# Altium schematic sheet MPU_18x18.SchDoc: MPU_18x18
size A3; DocumentNumber: MB1263; Revision: C-04; SheetNumber: 3; SheetTotal: 11; Project: STM32MP157-EVAL
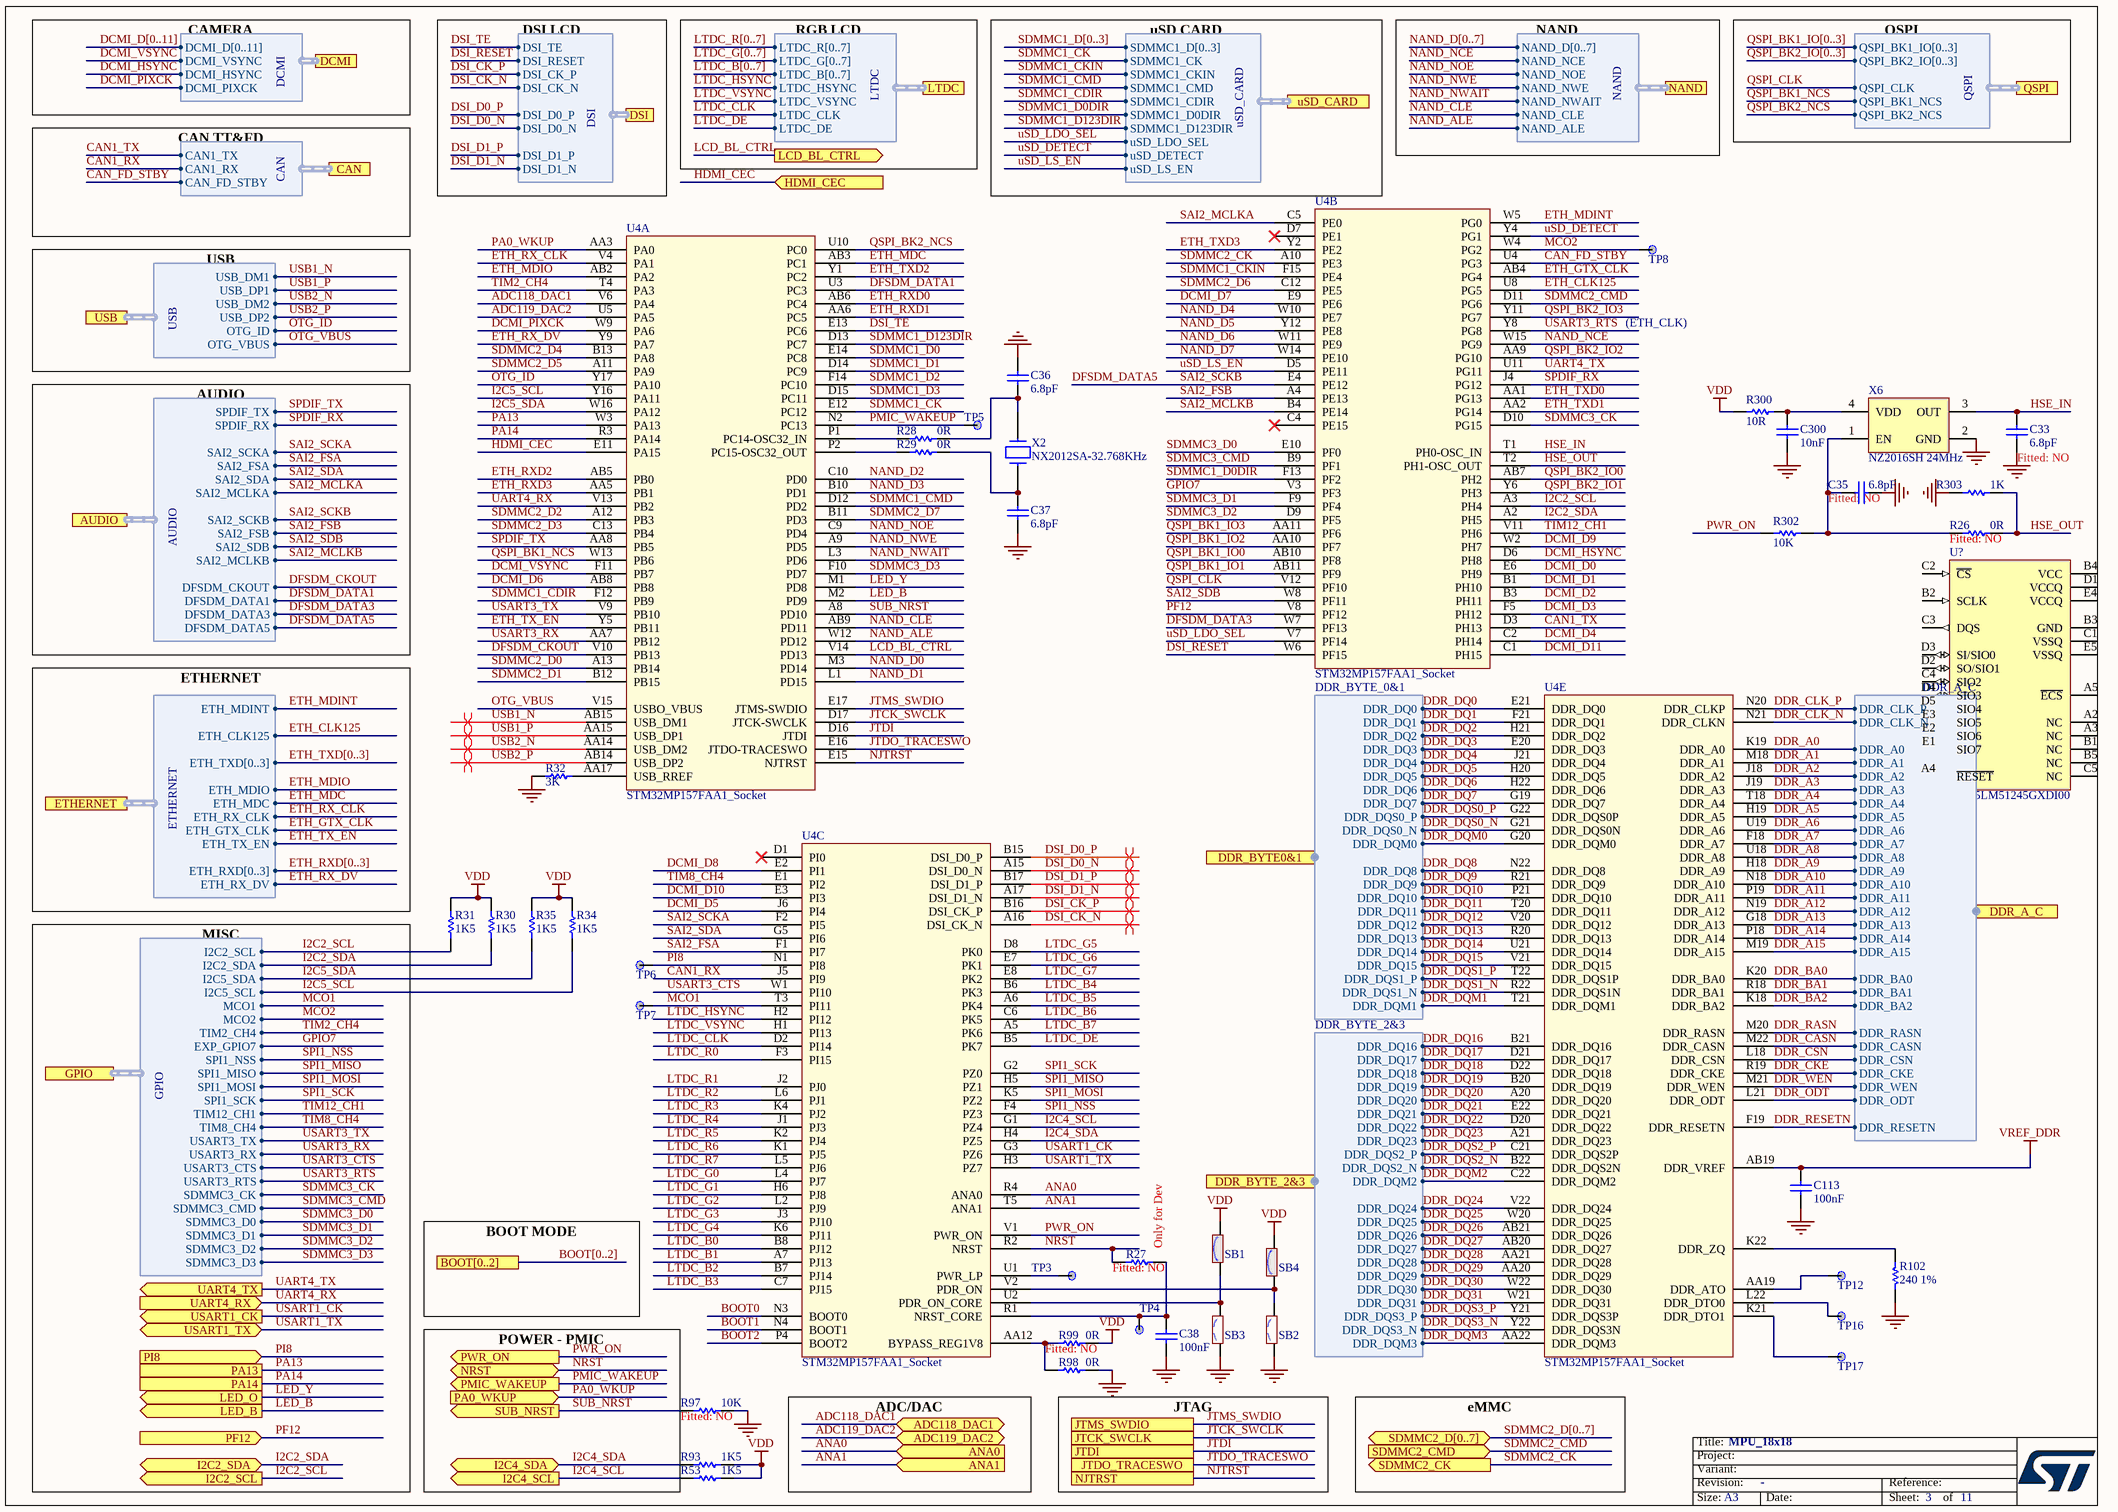
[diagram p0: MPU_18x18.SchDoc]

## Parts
C33  Fitted: NO  [C0402]  (hidden comment: 6.8pF)
C35  Fitted: NO  [C0402]  (hidden comment: 6.8pF)
C36  6.8pF  [C0402]
C37  6.8pF  [C0402]
C38  100nF  [C0402]
C113  100nF  [C0402]
C300  10nF  [C0402]
R26  0R  Fitted: NO  [R0402]
R27  Fitted: NO  [R0402]  (hidden comment: 0R)
R28  0R  [R0402]
R29  0R  [R0402]
R30  1K5  [R0402]
R31  1K5  [R0402]
R32  3K  [R0402]
R34  1K5  [R0402]
R35  1K5  [R0402]
R53  1K5  [R0402]
R93  1K5  [R0402]
R97  10K  Fitted: NO  [R0402]
R98  0R  [R0402]
R99  0R  Fitted: NO  [R0402]
R102  240 1%  [R0402]
R300  value 10R  [R0402]  (hidden comment: Resistor)
R302  10K  [R0402]
R303  1K  [R0402]
SB1  SB_ON  [SOLDER-BRIDGE_R0603-0R]  (value not drawn)
SB2  SB_OFF  [SOLDER-BRIDGE_R0603-0R]  (value not drawn)
SB3  SB_OFF  [SOLDER-BRIDGE_R0603-0R]  (value not drawn)
SB4  SB_ON  [SOLDER-BRIDGE_R0603-0R]  (value not drawn)
TP3  TP  [TP_SMD_1MM]  (value not drawn)  (no BOM)
TP4  TP  [TP_SMD_1MM]  (value not drawn)  (no BOM)
TP5  TP  [TP_SMD_1MM]  (value not drawn)  (no BOM)
TP6  TP  [TP_SMD_1MM]  (value not drawn)  (no BOM)
TP7  TP  [TP_SMD_1MM]  (value not drawn)  (no BOM)
TP8  TP  [TP_SMD_1MM]  (value not drawn)  (no BOM)
TP12  TP 0.6  [TP_SMD_0-6MM]  (value not drawn)  (no BOM)
TP16  TP 0.6  [TP_SMD_0-6MM]  (value not drawn)  (no BOM)
TP17  TP 0.6  [TP_SMD_0-6MM]  (value not drawn)  (no BOM)
U4  STM32MP157FAA1_Socket  [ICC_LFBGA448_18X18_STM32MP157BAA3_P080__SOCKET_IE_CS1627194MF]  (parts A,B,C,E of 5)
U?  value MX25LM51245GXDI00  [ICC_BGA24_5X5-BALL-ARRAY_6X8_P1]  (hidden comment: MX25xx51245GXDx00)
X2  NX2012SA-32.768KHz  [CRY_NX2012SA_2P]
X6  value NZ2016SH 24MHz  [CRY_NZ2016SH_4P]  (hidden comment: OSCILLATOR_4_PINS)

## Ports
ADC118_DAC1 (bidir), ADC119_DAC2 (bidir), ANA0 (in), ANA1 (in), AUDIO (harness AUDIO), BOOT[0..2], CAN (harness CAN), DCMI (harness DCMI), DDR_A_C (harness DDR_A_C), DDR_BYTE0&1 (harness DDR_BYTE_0&1), DDR_BYTE_2&3 (harness DDR_BYTE_2&3), DSI (harness DSI), ETHERNET (harness ETHERNET), GPIO (harness GPIO), HDMI_CEC (in), I2C2_SCL (out), I2C2_SDA (bidir), I2C4_SCL (out), I2C4_SDA (bidir), JTCK_SWCLK, JTDI, JTDO_TRACESWO, JTMS_SWDIO, LCD_BL_CTRL (out), LED_B (out), LED_O (out), LTDC (harness LTDC), NAND (harness NAND), NJTRST, NRST (bidir), PA0_WKUP (in), PA13, PA14, PF12 (in), PI8 (in), PMIC_WAKEUP (out), PWR_ON (out), QSPI (harness QSPI), SDMMC2_CK (out), SDMMC2_CMD (in), SDMMC2_D[0..7] (bidir), SUB_NRST (out), UART4_RX (in), UART4_TX (out), USART1_CK (out), USART1_TX (bidir), USB (harness USB), uSD_CARD (harness uSD_CARD)

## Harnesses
DDR_BYTE_0&1: DDR_DQ0, DDR_DQ1, DDR_DQ2, DDR_DQ3, DDR_DQ4, DDR_DQ5, DDR_DQ6, DDR_DQ7, DDR_DQS0_P, DDR_DQS0_N, DDR_DQM0, DDR_DQ8, DDR_DQ9, DDR_DQ10, DDR_DQ11, DDR_DQ12, DDR_DQ13, DDR_DQ14, DDR_DQ15, DDR_DQS1_P, DDR_DQS1_N, DDR_DQM1
DDR_BYTE_2&3: DDR_DQ16, DDR_DQ17, DDR_DQ18, DDR_DQ19, DDR_DQ20, DDR_DQ21, DDR_DQ22, DDR_DQ23, DDR_DQS2_P, DDR_DQS2_N, DDR_DQM2, DDR_DQ24, DDR_DQ25, DDR_DQ26, DDR_DQ27, DDR_DQ28, DDR_DQ29, DDR_DQ30, DDR_DQ31, DDR_DQS3_P, DDR_DQS3_N, DDR_DQM3
DDR_A_C: DDR_CLK_P, DDR_CLK_N, DDR_A0, DDR_A1, DDR_A2, DDR_A3, DDR_A4, DDR_A5, DDR_A6, DDR_A7, DDR_A8, DDR_A9, DDR_A10, DDR_A11, DDR_A12, DDR_A13, DDR_A14, DDR_A15, DDR_BA0, DDR_BA1, DDR_BA2, DDR_RASN, DDR_CASN, DDR_CSN, DDR_CKE, DDR_WEN, DDR_ODT, DDR_RESETN
GPIO: I2C2_SCL, I2C2_SDA, I2C5_SDA, MCO1, MCO2, TIM2_CH4, EXP_GPIO7, SPI1_NSS, SPI1_MISO, SPI1_MOSI, SPI1_SCK, TIM12_CH1, TIM8_CH4, USART3_TX, USART3_RX, USART3_CTS, USART3_RTS, SDMMC3_CK, SDMMC3_CMD, SDMMC3_D0, SDMMC3_D1, SDMMC3_D2, SDMMC3_D3, I2C5_SCL
ETHERNET: ETH_MDINT, ETH_CLK125, ETH_TXD[0..3], ETH_MDIO, ETH_MDC, ETH_RX_CLK, ETH_GTX_CLK, ETH_TX_EN, ETH_RXD[0..3], ETH_RX_DV
AUDIO: SPDIF_TX, SPDIF_RX, SAI2_SCKA, SAI2_FSA, SAI2_SDA, SAI2_SDB, SAI2_MCLKA, DFSDM_CKOUT, DFSDM_DATA1, DFSDM_DATA3, DFSDM_DATA5, SAI2_SCKB, SAI2_FSB, SAI2_MCLKB
DCMI: DCMI_D[0..11], DCMI_VSYNC, DCMI_HSYNC, DCMI_PIXCK
DSI: DSI_CK_P, DSI_CK_N, DSI_D0_P, DSI_D0_N, DSI_D1_P, DSI_D1_N, DSI_TE, DSI_RESET
LTDC: LTDC_R[0..7], LTDC_G[0..7], LTDC_B[0..7], LTDC_HSYNC, LTDC_VSYNC, LTDC_CLK, LTDC_DE
NAND: NAND_D[0..7], NAND_NCE, NAND_NOE, NAND_NWE, NAND_NWAIT, NAND_CLE, NAND_ALE
USB: USB_DM1, USB_DP1, USB_DM2, USB_DP2, OTG_ID, OTG_VBUS
QSPI: QSPI_BK1_IO[0..3], QSPI_BK2_IO[0..3], QSPI_CLK, QSPI_BK1_NCS, QSPI_BK2_NCS
uSD_CARD: SDMMC1_D[0..3], SDMMC1_CK, SDMMC1_CKIN, SDMMC1_CMD, SDMMC1_CDIR, SDMMC1_D0DIR, SDMMC1_D123DIR, uSD_LDO_SEL, uSD_DETECT, uSD_LS_EN
CAN: CAN1_TX, CAN1_RX, CAN_FD_STBY

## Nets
GND: C33.1 C35.1 C36.2 C37.1 C38.1 C113.1 C300.1 R32.1 R97.2 R98.2 R102.2 R303.2 SB2.1 SB3.1 X6.2(GND)
VDD: R30.2 R31.2 R34.2 R35.2 R53.1 R93.1 R99.2 R300.1 SB1.2 SB4.2
VREF_DDR: C113.2 U4.AB19(DDR_VREF)
ADC118_DAC1: U4.V6(PA4) ; port ADC118_DAC1
ADC119_DAC2: U4.U5(PA5) ; port ADC119_DAC2
ANA0: U4.R4(ANA0) ; port ANA0
ANA1: U4.T5(ANA1) ; port ANA1
BOOT0: U4.N3(BOOT0)
BOOT1: U4.N4(BOOT1)
BOOT2: U4.P4(BOOT2)
CAN1_RX: U4.J5(PI9) ; port CAN.CAN1_RX
CAN1_TX: U4.D3(PH13) ; port CAN.CAN1_TX
CAN_FD_STBY: U4.U4(PG3) ; port CAN.CAN_FD_STBY
DCMI_D0: U4.E6(PH9)
DCMI_D1: U4.B1(PH10)
DCMI_D2: U4.B3(PH11)
DCMI_D3: U4.F5(PH12)
DCMI_D4: U4.C2(PH14)
DCMI_D5: U4.J6(PI4)
DCMI_D6: U4.AB8(PB8)
DCMI_D7: U4.E9(PE6)
DCMI_D8: U4.E2(PI1)
DCMI_D9: U4.W2(PH7)
DCMI_D10: U4.E3(PI3)
DCMI_D11: U4.C1(PH15)
DCMI_HSYNC: U4.D6(PH8) ; port DCMI.DCMI_HSYNC
DCMI_PIXCK: U4.W9(PA6) ; port DCMI.DCMI_PIXCK
DCMI_VSYNC: U4.F11(PB7) ; port DCMI.DCMI_VSYNC
DDR_A0: U4.K19(DDR_A0) ; port DDR_A_C.DDR_A0
DDR_A1: U4.M18(DDR_A1) ; port DDR_A_C.DDR_A1
DDR_A2: U4.J18(DDR_A2) ; port DDR_A_C.DDR_A2
DDR_A3: U4.J19(DDR_A3) ; port DDR_A_C.DDR_A3
DDR_A4: U4.T18(DDR_A4) ; port DDR_A_C.DDR_A4
DDR_A5: U4.H19(DDR_A5) ; port DDR_A_C.DDR_A5
DDR_A6: U4.U19(DDR_A6) ; port DDR_A_C.DDR_A6
DDR_A7: U4.F18(DDR_A7) ; port DDR_A_C.DDR_A7
DDR_A8: U4.U18(DDR_A8) ; port DDR_A_C.DDR_A8
DDR_A9: U4.H18(DDR_A9) ; port DDR_A_C.DDR_A9
DDR_A10: U4.N18(DDR_A10) ; port DDR_A_C.DDR_A10
DDR_A11: U4.P19(DDR_A11) ; port DDR_A_C.DDR_A11
DDR_A12: U4.N19(DDR_A12) ; port DDR_A_C.DDR_A12
DDR_A13: U4.G18(DDR_A13) ; port DDR_A_C.DDR_A13
DDR_A14: U4.P18(DDR_A14) ; port DDR_A_C.DDR_A14
DDR_A15: U4.M19(DDR_A15) ; port DDR_A_C.DDR_A15
DDR_BA0: U4.K20(DDR_BA0) ; port DDR_A_C.DDR_BA0
DDR_BA1: U4.R18(DDR_BA1) ; port DDR_A_C.DDR_BA1
DDR_BA2: U4.K18(DDR_BA2) ; port DDR_A_C.DDR_BA2
DDR_CASN: U4.M22(DDR_CASN) ; port DDR_A_C.DDR_CASN
DDR_CKE: U4.R19(DDR_CKE) ; port DDR_A_C.DDR_CKE
DDR_CLK_N: U4.N21(DDR_CLKN) ; port DDR_A_C.DDR_CLK_N
DDR_CLK_P: U4.N20(DDR_CLKP) ; port DDR_A_C.DDR_CLK_P
DDR_CSN: U4.L18(DDR_CSN) ; port DDR_A_C.DDR_CSN
DDR_DQ0: U4.E21(DDR_DQ0) ; port DDR_BYTE0&1.DDR_DQ0
DDR_DQ1: U4.F21(DDR_DQ1) ; port DDR_BYTE0&1.DDR_DQ1
DDR_DQ2: U4.H21(DDR_DQ2) ; port DDR_BYTE0&1.DDR_DQ2
DDR_DQ3: U4.E20(DDR_DQ3) ; port DDR_BYTE0&1.DDR_DQ3
DDR_DQ4: U4.J21(DDR_DQ4) ; port DDR_BYTE0&1.DDR_DQ4
DDR_DQ5: U4.H20(DDR_DQ5) ; port DDR_BYTE0&1.DDR_DQ5
DDR_DQ6: U4.H22(DDR_DQ6) ; port DDR_BYTE0&1.DDR_DQ6
DDR_DQ7: U4.G19(DDR_DQ7) ; port DDR_BYTE0&1.DDR_DQ7
DDR_DQ8: U4.N22(DDR_DQ8) ; port DDR_BYTE0&1.DDR_DQ8
DDR_DQ9: U4.R21(DDR_DQ9) ; port DDR_BYTE0&1.DDR_DQ9
DDR_DQ10: U4.P21(DDR_DQ10) ; port DDR_BYTE0&1.DDR_DQ10
DDR_DQ11: U4.T20(DDR_DQ11) ; port DDR_BYTE0&1.DDR_DQ11
DDR_DQ12: U4.V20(DDR_DQ12) ; port DDR_BYTE0&1.DDR_DQ12
DDR_DQ13: U4.R20(DDR_DQ13) ; port DDR_BYTE0&1.DDR_DQ13
DDR_DQ14: U4.U21(DDR_DQ14) ; port DDR_BYTE0&1.DDR_DQ14
DDR_DQ15: U4.V21(DDR_DQ15) ; port DDR_BYTE0&1.DDR_DQ15
DDR_DQ16: U4.B21(DDR_DQ16) ; port DDR_BYTE_2&3.DDR_DQ16
DDR_DQ17: U4.D21(DDR_DQ17) ; port DDR_BYTE_2&3.DDR_DQ17
DDR_DQ18: U4.D22(DDR_DQ18) ; port DDR_BYTE_2&3.DDR_DQ18
DDR_DQ19: U4.B20(DDR_DQ19) ; port DDR_BYTE_2&3.DDR_DQ19
DDR_DQ20: U4.A20(DDR_DQ20) ; port DDR_BYTE_2&3.DDR_DQ20
DDR_DQ21: U4.E22(DDR_DQ21) ; port DDR_BYTE_2&3.DDR_DQ21
DDR_DQ22: U4.D20(DDR_DQ22) ; port DDR_BYTE_2&3.DDR_DQ22
DDR_DQ23: U4.A21(DDR_DQ23) ; port DDR_BYTE_2&3.DDR_DQ23
DDR_DQ24: U4.V22(DDR_DQ24) ; port DDR_BYTE_2&3.DDR_DQ24
DDR_DQ25: U4.W20(DDR_DQ25) ; port DDR_BYTE_2&3.DDR_DQ25
DDR_DQ26: U4.AB21(DDR_DQ26) ; port DDR_BYTE_2&3.DDR_DQ26
DDR_DQ27: U4.AB20(DDR_DQ27) ; port DDR_BYTE_2&3.DDR_DQ27
DDR_DQ28: U4.AA21(DDR_DQ28) ; port DDR_BYTE_2&3.DDR_DQ28
DDR_DQ29: U4.AA20(DDR_DQ29) ; port DDR_BYTE_2&3.DDR_DQ29
DDR_DQ30: U4.W22(DDR_DQ30) ; port DDR_BYTE_2&3.DDR_DQ30
DDR_DQ31: U4.W21(DDR_DQ31) ; port DDR_BYTE_2&3.DDR_DQ31
DDR_DQM0: U4.G20(DDR_DQM0) ; port DDR_BYTE0&1.DDR_DQM0
DDR_DQM1: U4.T21(DDR_DQM1) ; port DDR_BYTE0&1.DDR_DQM1
DDR_DQM2: U4.C22(DDR_DQM2) ; port DDR_BYTE_2&3.DDR_DQM2
DDR_DQM3: U4.AA22(DDR_DQM3) ; port DDR_BYTE_2&3.DDR_DQM3
DDR_DQS0_N: U4.G21(DDR_DQS0N) ; port DDR_BYTE0&1.DDR_DQS0_N
DDR_DQS0_P: U4.G22(DDR_DQS0P) ; port DDR_BYTE0&1.DDR_DQS0_P
DDR_DQS1_N: U4.R22(DDR_DQS1N) ; port DDR_BYTE0&1.DDR_DQS1_N
DDR_DQS1_P: U4.T22(DDR_DQS1P) ; port DDR_BYTE0&1.DDR_DQS1_P
DDR_DQS2_N: U4.B22(DDR_DQS2N) ; port DDR_BYTE_2&3.DDR_DQS2_N
DDR_DQS2_P: U4.C21(DDR_DQS2P) ; port DDR_BYTE_2&3.DDR_DQS2_P
DDR_DQS3_N: U4.Y22(DDR_DQS3N) ; port DDR_BYTE_2&3.DDR_DQS3_N
DDR_DQS3_P: U4.Y21(DDR_DQS3P) ; port DDR_BYTE_2&3.DDR_DQS3_P
DDR_ODT: U4.L21(DDR_ODT) ; port DDR_A_C.DDR_ODT
DDR_RASN: U4.M20(DDR_RASN) ; port DDR_A_C.DDR_RASN
DDR_RESETN: U4.F19(DDR_RESETN) ; port DDR_A_C.DDR_RESETN
DDR_WEN: U4.M21(DDR_WEN) ; port DDR_A_C.DDR_WEN
DFSDM_CKOUT: U4.V10(PB13) ; port AUDIO.DFSDM_CKOUT
DFSDM_DATA1: U4.U3(PC3) ; port AUDIO.DFSDM_DATA1
DFSDM_DATA3: U4.W7(PF13) ; port AUDIO.DFSDM_DATA3
DFSDM_DATA5: U4.E4(PE12) ; port AUDIO.DFSDM_DATA5, port AUDIO.SAI2_SCKB  [also labelled SAI2_SCKB]
DSI_CK_N: U4.A16(DSI_CK_N) ; port DSI.DSI_CK_N
DSI_CK_P: U4.B16(DSI_CK_P) ; port DSI.DSI_CK_P
DSI_D0_N: U4.A15(DSI_D0_N) ; port DSI.DSI_D0_N
DSI_D0_P: U4.B15(DSI_D0_P) ; port DSI.DSI_D0_P
DSI_D1_N: U4.A17(DSI_D1_N) ; port DSI.DSI_D1_N
DSI_D1_P: U4.B17(DSI_D1_P) ; port DSI.DSI_D1_P
DSI_RESET: U4.W6(PF15) ; port DSI.DSI_RESET
DSI_TE: U4.E13(PC6) ; port DSI.DSI_TE
ETH_CLK125: U4.U8(PG5) ; port ETHERNET.ETH_CLK125
ETH_GTX_CLK: U4.AB4(PG4) ; port ETHERNET.ETH_GTX_CLK
ETH_MDC: U4.AB3(PC1) ; port ETHERNET.ETH_MDC
ETH_MDINT: U4.W5(PG0) ; port ETHERNET.ETH_MDINT
ETH_MDIO: U4.AB2(PA2) ; port ETHERNET.ETH_MDIO
ETH_RX_CLK: U4.V4(PA1) ; port ETHERNET.ETH_RX_CLK
ETH_RX_DV: U4.Y9(PA7) ; port ETHERNET.ETH_RX_DV
ETH_RXD0: U4.AB6(PC4)
ETH_RXD1: U4.AA6(PC5)
ETH_RXD2: U4.AB5(PB0)
ETH_RXD3: U4.AA5(PB1)
ETH_TX_EN: U4.Y5(PB11) ; port ETHERNET.ETH_TX_EN
ETH_TXD0: U4.AA1(PG13)
ETH_TXD1: U4.AA2(PG14)
ETH_TXD2: U4.Y1(PC2)
ETH_TXD3: U4.Y2(PE2)
GPIO7: U4.V3(PF3) ; port GPIO.EXP_GPIO7
HDMI_CEC: U4.E11(PA15) ; port HDMI_CEC
HSE_IN: C33.2 U4.T1(PH0-OSC_IN) X6.3(OUT)
HSE_OUT: R26.2 R303.1 U4.T2(PH1-OSC_OUT)
I2C2_SCL: R31.1 U4.A3(PH4) ; port I2C2_SCL, port GPIO.I2C2_SCL
I2C2_SDA: R30.1 U4.A2(PH5) ; port I2C2_SDA, port GPIO.I2C2_SDA
I2C4_SCL: R53.2 U4.G1(PZ4) ; port I2C4_SCL
I2C4_SDA: R93.2 U4.H4(PZ5) ; port I2C4_SDA
I2C5_SCL: R34.1 U4.Y16(PA11) ; port GPIO.I2C5_SCL
I2C5_SDA: R35.1 U4.W16(PA12) ; port GPIO.I2C5_SDA
JTCK_SWCLK: U4.D17(JTCK-SWCLK) ; port JTCK_SWCLK
JTDI: U4.D16(JTDI) ; port JTDI
JTDO_TRACESWO: U4.E16(JTDO-TRACESWO) ; port JTDO_TRACESWO
JTMS_SWDIO: U4.E17(JTMS-SWDIO) ; port JTMS_SWDIO
LCD_BL_CTRL: U4.V14(PD13) ; port LCD_BL_CTRL
LED_B: U4.M2(PD9) ; port LED_B
LED_Y: U4.M1(PD8) ; port LED_O
LTDC_B0: U4.B8(PJ12)
LTDC_B1: U4.A7(PJ13)
LTDC_B2: U4.B7(PJ14)
LTDC_B3: U4.C7(PJ15)
LTDC_B4: U4.B6(PK3)
LTDC_B5: U4.A6(PK4)
LTDC_B6: U4.C6(PK5)
LTDC_B7: U4.A5(PK6)
LTDC_CLK: U4.D2(PI14) ; port LTDC.LTDC_CLK
LTDC_DE: U4.B5(PK7) ; port LTDC.LTDC_DE
LTDC_G0: U4.L4(PJ7)
LTDC_G1: U4.H6(PJ8)
LTDC_G2: U4.L2(PJ9)
LTDC_G3: U4.J3(PJ10)
LTDC_G4: U4.K6(PJ11)
LTDC_G5: U4.D8(PK0)
LTDC_G6: U4.E7(PK1)
LTDC_G7: U4.E8(PK2)
LTDC_HSYNC: U4.H2(PI12) ; port LTDC.LTDC_HSYNC
LTDC_R0: U4.F3(PI15)
LTDC_R1: U4.J2(PJ0)
LTDC_R2: U4.L6(PJ1)
LTDC_R3: U4.K4(PJ2)
LTDC_R4: U4.J1(PJ3)
LTDC_R5: U4.K2(PJ4)
LTDC_R6: U4.K1(PJ5)
LTDC_R7: U4.L5(PJ6)
LTDC_VSYNC: U4.H1(PI13) ; port LTDC.LTDC_VSYNC
MCO1: TP7.1 U4.T3(PI11) ; port GPIO.MCO1
MCO2: TP8.1 U4.W4(PG2) ; port GPIO.MCO2
NAND_ALE: U4.W12(PD12) ; port NAND.NAND_ALE
NAND_CLE: U4.AB9(PD11) ; port NAND.NAND_CLE
NAND_D0: U4.M3(PD14)
NAND_D1: U4.L1(PD15)
NAND_D2: U4.C10(PD0)
NAND_D3: U4.B10(PD1)
NAND_D4: U4.W10(PE7)
NAND_D5: U4.Y12(PE8)
NAND_D6: U4.W11(PE9)
NAND_D7: U4.W14(PE10)
NAND_NCE: U4.W15(PG9) ; port NAND.NAND_NCE
NAND_NOE: U4.C9(PD4) ; port NAND.NAND_NOE
NAND_NWAIT: U4.L3(PD6) ; port NAND.NAND_NWAIT
NAND_NWE: U4.A9(PD5) ; port NAND.NAND_NWE
NJTRST: U4.E15(NJTRST) ; port NJTRST
NRST: R27.2 U4.R2(NRST) ; port NRST
OTG_ID: U4.Y17(PA10) ; port USB.OTG_ID
OTG_VBUS: U4.V15(USBO_VBUS) ; port USB.OTG_VBUS
PA0_WKUP: U4.AA3(PA0) ; port PA0_WKUP
PA13: U4.W3(PA13) ; port PA13
PA14: U4.R3(PA14) ; port PA14
PF12: U4.V8(PF12) ; port PF12
PI8: TP6.1 U4.N1(PI8) ; port PI8
PMIC_WAKEUP: TP5.1 U4.N2(PC13) ; port PMIC_WAKEUP
PWR_ON: R302.1 U4.V1(PWR_ON) ; port PWR_ON
QSPI_BK1_IO0: U4.AB10(PF8)
QSPI_BK1_IO1: U4.AB11(PF9)
QSPI_BK1_IO2: U4.AA10(PF7)
QSPI_BK1_IO3: U4.AA11(PF6)
QSPI_BK1_NCS: U4.W13(PB6) ; port QSPI.QSPI_BK1_NCS
QSPI_BK2_IO0: U4.AB7(PH2)
QSPI_BK2_IO1: U4.Y6(PH3)
QSPI_BK2_IO2: U4.AA9(PG10)
QSPI_BK2_IO3: U4.Y11(PG7)
QSPI_BK2_NCS: U4.U10(PC0) ; port QSPI.QSPI_BK2_NCS
QSPI_CLK: U4.V12(PF10) ; port QSPI.QSPI_CLK
SAI2_FSA: U4.F1(PI7) ; port AUDIO.SAI2_FSA
SAI2_FSB: U4.A4(PE13) ; port AUDIO.SAI2_FSB
SAI2_MCLKA: U4.C5(PE0) ; port AUDIO.SAI2_MCLKA
SAI2_MCLKB: U4.B4(PE14) ; port AUDIO.SAI2_MCLKB
SAI2_SCKA: U4.F2(PI5) ; port AUDIO.SAI2_SCKA
SAI2_SDA: U4.G5(PI6) ; port AUDIO.SAI2_SDA
SAI2_SDB: U4.W8(PF11) ; port AUDIO.SAI2_SDB
SDMMC1_CDIR: U4.F12(PB9) ; port uSD_CARD.SDMMC1_CDIR
SDMMC1_CK: U4.E12(PC12) ; port uSD_CARD.SDMMC1_CK
SDMMC1_CKIN: U4.F15(PE4) ; port uSD_CARD.SDMMC1_CKIN
SDMMC1_CMD: U4.D12(PD2) ; port uSD_CARD.SDMMC1_CMD
SDMMC1_D0: U4.E14(PC8)
SDMMC1_D0DIR: U4.F13(PF2) ; port uSD_CARD.SDMMC1_D0DIR
SDMMC1_D1: U4.D14(PC9)
SDMMC1_D2: U4.F14(PC10)
SDMMC1_D3: U4.D15(PC11)
SDMMC1_D123DIR: U4.D13(PC7) ; port uSD_CARD.SDMMC1_D123DIR
SDMMC2_CK: U4.A10(PE3) ; port SDMMC2_CK
SDMMC2_CMD: U4.D11(PG6) ; port SDMMC2_CMD
SDMMC2_D0: U4.A13(PB14)
SDMMC2_D1: U4.B12(PB15)
SDMMC2_D2: U4.A12(PB3)
SDMMC2_D3: U4.C13(PB4)
SDMMC2_D4: U4.B13(PA8)
SDMMC2_D5: U4.A11(PA9)
SDMMC2_D6: U4.C12(PE5)
SDMMC2_D7: U4.B11(PD3)
SDMMC3_CK: U4.D10(PG15) ; port GPIO.SDMMC3_CK
SDMMC3_CMD: U4.B9(PF1) ; port GPIO.SDMMC3_CMD
SDMMC3_D0: U4.E10(PF0) ; port GPIO.SDMMC3_D0
SDMMC3_D1: U4.F9(PF4) ; port GPIO.SDMMC3_D1
SDMMC3_D2: U4.D9(PF5) ; port GPIO.SDMMC3_D2
SDMMC3_D3: U4.F10(PD7) ; port GPIO.SDMMC3_D3
SPDIF_RX: U4.J4(PG12) ; port AUDIO.SPDIF_RX
SPDIF_TX: U4.AA8(PB5) ; port AUDIO.SPDIF_TX
SPI1_MISO: U4.H5(PZ1) ; port GPIO.SPI1_MISO
SPI1_MOSI: U4.K5(PZ2) ; port GPIO.SPI1_MOSI
SPI1_NSS: U4.F4(PZ3) ; port GPIO.SPI1_NSS
SPI1_SCK: U4.G2(PZ0) ; port GPIO.SPI1_SCK
SUB_NRST: R97.1 U4.A8(PD10) ; port SUB_NRST
TIM2_CH4: U4.T4(PA3) ; port GPIO.TIM2_CH4
TIM8_CH4: U4.E1(PI2) ; port GPIO.TIM8_CH4
TIM12_CH1: U4.V11(PH6) ; port GPIO.TIM12_CH1
UART4_RX: U4.V13(PB2) ; port UART4_RX
UART4_TX: U4.U11(PG11) ; port UART4_TX
USART1_CK: U4.G3(PZ6) ; port USART1_CK
USART1_TX: U4.H3(PZ7) ; port USART1_TX
USART3_CTS: U4.W1(PI10) ; port GPIO.USART3_CTS
USART3_RTS: U4.Y8(PG8) ; port GPIO.USART3_RTS
USART3_RX: U4.AA7(PB12) ; port GPIO.USART3_RX
USART3_TX: U4.V9(PB10) ; port GPIO.USART3_TX
USB1_N: U4.AB15(USB_DM1) ; port USB.USB_DM1
USB1_P: U4.AA15(USB_DP1) ; port USB.USB_DP1
USB2_N: U4.AA14(USB_DM2) ; port USB.USB_DM2
USB2_P: U4.AB14(USB_DP2) ; port USB.USB_DP2
uSD_DETECT: U4.Y4(PG1) ; port uSD_CARD.uSD_DETECT
uSD_LDO_SEL: U4.V7(PF14) ; port uSD_CARD.uSD_LDO_SEL
uSD_LS_EN: U4.D5(PE11) ; port uSD_CARD.uSD_LS_EN
NetC35_2: C35.2 R26.1 R302.2 X6.1(EN)
NetC36_1: C36.1 R28.2 X2.1
NetC37_2: C37.2 R29.2 X2.2
NetC38_2: C38.2 R27.1 TP4.1 U4.R1(NRST_CORE)
NetC300_2: C300.2 R300.2 X6.4(VDD)
NetR28_1: R28.1 U4.P1(PC14-OSC32_IN)
NetR29_1: R29.1 U4.P2(PC15-OSC32_OUT)
NetR32_2: R32.2 U4.AA17(USB_RREF)
NetR98_1: R98.1 R99.1 U4.AA12(BYPASS_REG1V8)
NetR102_1: R102.1 U4.K22(DDR_ZQ)
NetSB1_1: SB1.1 SB3.2 U4.U2(PDR_ON_CORE)
NetSB2_2: SB2.2 SB4.1 U4.V2(PDR_ON)
NetTP3_1: TP3.1 U4.U1(PWR_LP)
NetTP12_1: TP12.1 U4.AA19(DDR_ATO)
NetTP16_1: TP16.1 U4.L22(DDR_DTO0)
NetTP17_1: TP17.1 U4.K21(DDR_DTO1)

Not connected (* = marked no-connect by the designer): U4 C4(PE15)* D1(PI0)* D7(PE1)*; U? A2(NC) A3(NC) A4(~{RESET}) A5(~{ECS}) B1(NC) B2(SCLK) B3(GND) B4(VCC) B5(NC) C1(VSSQ) C2(~{CS}) C3(DQS) C4(SIO2) C5(NC) D1(VCCQ) D2(SO/SIO1) D3(SI/SIO0) D4(SIO3) D5(SIO4) E1(SIO7) E2(SIO6) E3(SIO5) E4(VCCQ) E5(VSSQ)

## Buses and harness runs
bus BOOT[0..2] = port BOOT[0..2]
bus DCMI_D[0..11]
bus ETH_RXD[0..3]
bus ETH_TXD[0..3]
bus LTDC_B[0..7]
bus LTDC_G[0..7]
bus LTDC_R[0..7]
bus NAND_D[0..7]
bus QSPI_BK1_IO[0..3]
bus QSPI_BK2_IO[0..3]
bus SDMMC1_D[0..3]
bus SDMMC2_D[0..7] = port SDMMC2_D[0..7]

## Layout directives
differential pair: DSI_CK_N, DSI_CK_P, DSI_D0_N, DSI_D0_P, DSI_D1_N, DSI_D1_P, USB1_N, USB1_P, USB2_N, USB2_P

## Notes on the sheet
- CAMERA
- RGB LCD
- NAND
- QSPI
- CAN TT&FD
- DSI LCD
- (near U4) uSD CARD
- USB
- (ETH_CLK)
- AUDIO
- (near R31) ETHERNET
- (near R27) Only for Dev
- BOOT MODE
- (near R31) MISC
- POWER - PMIC
- ADC/DAC
- (near R98) JTAG
- eMMC

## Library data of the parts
C33 C35 = Cap_6.8pF_NPO_0402: Capacitor, MLCC, 6.8pF, 50V, NPO, +-0.25pF, 0402, T=0.5mm; Manuf_Part_1: CC0402CRNPO9BN6R8; Manuf_1: YAGEO; Ordered_By: Subcon
C36 C37 = Cap_6.8pF_NPO_0402: Capacitor, MLCC, 6.8pF, 50V, NPO, +-0.25pF, 0402, T=0.5mm; Manuf_Part_1: CC0402CRNPO9BN6R8; Manuf_1: YAGEO; Fitted: Yes; Ordered_By: Subcon
C38 C113 = Cap_100nF_X7R_10%_0402: Capacitor,100nF,16V,X7R,10%,0402,YAGEO; Manuf_Part_1: CC0402KRX7R7BB104; Fitted: YES; Ordered_By: Subcon
C300 = Cap_10nF_X7R_10%_0402: Capacitor,10nF,16V,X7R,10%,0402,YAGEO; Manuf_Part_1: CC0402KRX7R7BB103; Fitted: YES; Ordered_By: Subcon
R26 R27 R99 = Res_0_5%_0402: Resistor,0R,0402,5%,YAGEO; Manuf_Part_1: RC0402JR-070RL; Order_Code: 2363467; Ordered_By: Subcon
R28 R29 R98 = Res_0_5%_0402: Resistor,0R,0402,5%,YAGEO; Manuf_Part_1: RC0402JR-070RL; Order_Code: 2363467; Fitted: YES; Ordered_By: Subcon
R30 R31 R34 R35 R53 R93 = Res_1K5_1%_0402: Resistor,1K5,0402,1%,YAGEO; Manuf_Part_1: RC0402FR-071K5L; Fitted: YES; Ordered_By: Subcon
R32 = Res_3K_1%_0402: Resistor,3K,0402,1%,YAGEO; Manuf_Part_1: RC0402FR-073KL; Order_Code: 1458777; Fitted: YES; Ordered_By: Subcon
R97 = Res_10K_1%_0402: Resistor,10K,0402,1%,YAGEO; Manuf_Part_1: RC0402FR-0710KL; Ordered_By: Subcon; Order_Code: 9239359RL
R102 = Res_240_1%_0402: Resistor,240R,0402,1%,YAGEO; Manuf_Part_1: RC0402FR-07240RL; Value: 240; Fitted: YES; Ordered_By: Subcon
R300 = Res_10R_1%_0402: Resistor,10R,0402,1%,1/16W; Manuf_Part_1: RC0402FR-0710RL; Manuf_1: YAGEO; Ordered_By: Subcon; Fitted: YES
R302 = Res_10K_1%_0402: Resistor,10K,0402,1%,YAGEO; Manuf_Part_1: RC0402FR-0710KL; Fitted: YES; Ordered_By: Subcon; Order_Code: 9239359RL
R303 = Res_1K_1%_0402: Resistor,1K,0402,1%,YAGEO; Manuf_Part_1: RC0402FR-071KL; Fitted: YES; Ordered_By: Subcon
SB1 SB4 = SB_ON: Solder Bridge ON; Fitted: YES; Ordered_by: Subcon
SB2 SB3 = SB_OFF: Solder Bridge OFF; Fitted: NO; Ordered_By: Subcon; Solder: NO
TP3-TP8 = TP 1mm: Test Point; Fitted: YES
TP12 TP16 TP17 = TP 0.6mm: Test Point; Fitted: YES
U4 = STM32MP157FAA1_Socket: MPU LFBGA18x18 with crypto-Increased Frequency; Manuf_1: ST; ECCN_US/EU: 5A002A4/5A002A4; Fitted: YES; Ordered_By: Subcon
U? = MCD-00246: Memory,Octo-SPI-NOR,512Mb,2048x16,133MHz,3V,DTR,BGA24, CMOS MXSMIO; Part_Type: IC; Part_Preference: Recommended; Manufacturer: MACRONIX; Component_Country_Of_Origin: Unknown; ShowFields: YES; ID: 2623
X2 = XTAL_32K_NX2012SA_527: Crystal 32.768kHz, 6pF, +/-20ppm@25°C; -0.04ppm/°C² ; ESRmax :70Kohm; Manuf_1: NDK; Manuf_Part_1: NX2012SA 32.768kHz EXS00A-MU00527; Ordered_By: Subcon; Fitted: YES
X6 = OSCILLATOR_4_PINS: Oscillator 24Mhz, +-50ppm, Vcc:3.3V typ (1.62V min), square wave: [0.1Vcc;0.9Vcc], Enable pin; Part_Type: Crystal_Osc; Manuf_Part_1: NZ2016SH 24MHz END4869F; Manuf_1: NDK; Ordered_By: Subcon; Fitted: YES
